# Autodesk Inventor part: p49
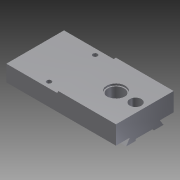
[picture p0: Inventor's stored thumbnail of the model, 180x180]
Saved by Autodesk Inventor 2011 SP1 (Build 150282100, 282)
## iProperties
Created: 2014-01
Part Number: p49
Document SubType Name: Modeling
Designer: Administrator
Density: 1 g/cm^3
Author: Administrator
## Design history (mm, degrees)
sketch "草图1"
  geometry: L1 (0, 25)-(95, 25); L2 (95, 25)-(95, -25); L3 (95, -25)-(0, -25); L4 (0, -25)-(0, 25); 2 further points
  constraints: 8 end point, 2 parallel, 1 coincident, 1 horizontal, 1 midpoint, 1 perpendicular
  dimensions: "d0" = 95 distance of L1.start L1.end; "d1" = 50 distance of L3.end L1.start
extrude "拉伸1" new body sketch "草图1" distance "d2" = 19; taper "d3" = 0 deg
sketch "草图2"
  geometry: L1 (95, 25)-(95, -25) reference; L2 (45, 25)-(95, 25); L3 (95, 25)-(95, -25); L4 (95, -25)-(45, -25); L5 (45, -25)-(45, 25); 2 further points
  constraints: 8 end point, 2 midpoint, 2 parallel, 1 horizontal, 1 perpendicular
  dimensions: "d4" = 50 distance of L2.start L2.end; "d5" = 50 distance of L4.end L2.start
extrude "拉伸2" join sketch "草图2" distance "d6" = 2; taper "d7" = 0 deg
fillet "圆角1" dims "d8" = 2
sketch "草图5"
  geometry: L1 (25, 0)-(25, 19) reference; L2 (-25, 19)-(25, 19) reference; L3 (25, 5)-(13, 5); L4 (13, 5)-(16.2, 0); L5 (-25, 0)-(25, 0) reference; 1 further point
  constraints: 4 end point, 2 point on line, 1 parallel
  dimensions: "d12" = 14 distance between parallel lines of L2 L3
extrude "拉伸3" cut sketch "草图5" stored distance "d15" = 10; taper "d16" = 0 deg
mirror "镜像1"
sketch "草图6"
  geometry: L1 (-19, 8.8)-(-19, 41.2) reference; L2 (-17.5, 33)-(-19, 33); L3 (-19, 33)-(-19, 17); L4 (-19, 17)-(-17.5, 17); L5 (-17.5, 17)-(-17.5, 33); 2 further points
  constraints: 8 end point, 2 midpoint, 2 parallel, 1 horizontal, 1 perpendicular
  dimensions: "d17" = 16 distance of L2.end L3.end; "d18" = 1.5 distance of L3.end L4.end
extrude "拉伸4" cut sketch "草图6" stored distance "d19" = 10; taper "d20" = 0 deg
sketch "草图7"
  geometry: L1 (8, 1.5)-(-8, 1.5) reference; L2 (8, 1.5)-(-8, 1.5); L3 (-8, 1.5)-(-8, 11.5); L4 (-8, 11.5)-(8, 11.5); L5 (8, 11.5)-(8, 1.5); 2 further points
  constraints: 8 end point, 2 midpoint, 2 parallel, 1 horizontal, 1 perpendicular
  dimensions: "d21" = 16 distance of L3.end L4.end; "d22" = 10 distance of L2.end L3.end
extrude "拉伸5" cut sketch "草图7" distance "d23" = 52; taper "d24" = 0 deg
fillet "圆角2" dims "d25" = 1.5
fillet "圆角3" dims "d26" = 1.5
hole "Hole1" diameter "d29" = 14; stored, may be unused: countersink angle "d33" = 90 deg, drill point angle "d35" = 0 deg; dims "d27" = 25, "d28" = 25, "d30" = 6, "d31" = 16, "d32" = 1.5, "d34" = 16
sketch "草图8"
  geometry: C1 r 10.5 at (70.008, 0); 1 further point
  constraints: 1 centre point
  dimensions: "d36" = 21 diameter of C1
extrude "拉伸6" cut sketch "草图8" distance "d37" = 5; taper "d38" = 0 deg
hole "Hole2" diameter "d41" = 4; stored, may be unused: countersink angle "d45" = 90 deg, drill point angle "d47" = 118 deg; dims "d39" = 32, "d40" = 5, "d42" = 6, "d43" = 16, "d44" = 1.5, "d46" = 16
mirror "镜像2"
hole "Hole3" diameter "d50" = 3.242; stored, may be unused: countersink angle "d54" = 90 deg, drill point angle "d56" = 118 deg; dims "d48" = 5, "d49" = 5, "d51" = 7, "d52" = 16, "d53" = 1.5, "d55" = 9
mirror "镜像3"
sketch "草图9"
  geometry: L1 (95, 25)-(95, -25) reference; C1 r 5 at (87, 0); 1 further point
  constraints: 1 centre point
  dimensions: "d57" = 10 diameter of C1; "d58" = 8 distance from line of L1 C1.centre
extrude "拉伸7" cut sketch "草图9" distance "d59" = 10; taper "d60" = 0 deg
hole "Hole4" diameter "d63" = 5; stored, may be unused: countersink angle "d67" = 90 deg, drill point angle "d69" = 118 deg; dims "d61" = 10, "d62" = 10, "d64" = 7, "d65" = 16, "d66" = 1.5, "d68" = 4
sketch "草图10"
  geometry: C1 r 2.5 at (0, 0) reference; C2 r 1.237 at (-3.737, 0); 1 further point
  constraints: 1 centre point, 1 tangent
extrude "拉伸8" cut sketch "草图10" stored distance "d70" = 10; taper "d71" = 0 deg
sketch "草图11"
  geometry: C1 r 1.212 at (3.788, 0); 2 further points
  constraints: 1 centre point
extrude "拉伸9" cut sketch "草图11" stored distance "d72" = 10; taper "d73" = 0 deg
node "实体1"
